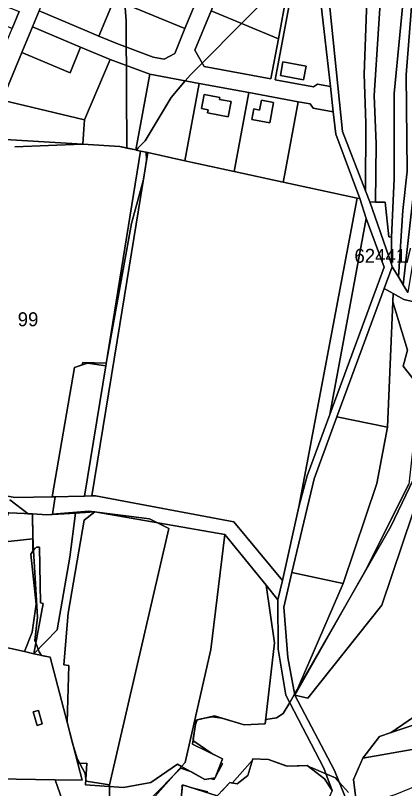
# Model space of a CAD drawing. Extents: x -502026 to -497664, y -1143484 to -1138019.
# Drawn here: x -498740.2 to -498516.2, y -1141619.2 to -1141174.4 of the extents above; entities that cross this region are included whole.
import ezdxf

# ---------------------------------------------------------------- set-up
doc = ezdxf.new("R2010")
doc.units = 0
for name, color, linetype in [('25', 7, 'Continuous'), ('31', 7, 'Continuous'), ('37', 7, 'Continuous'), ('43', 7, 'Continuous'), ('49', 7, 'Continuous'), ('55', 7, 'Continuous'), ('62', 7, 'Continuous'), ('7', 7, 'Continuous')]:
    doc.layers.add(name, color=color, linetype=linetype)

msp = doc.modelspace()

# ---------------------------------------------------------------- linework, layer by layer
at = {"layer": '25'}
for points in [[(-498750.53, -1141150.51), (-498755.96, -1141164.93), (-498738.05, -1141172.05), (-498742.03, -1141181.8), (-498793.83, -1141161.35), (-498790.27, -1141151.29), (-498778.95, -1141139.15)], [(-498730.32, -1141461.17), (-498730.31, -1141475.48), (-498755.37, -1141478.17), (-498750.65, -1141467.55), (-498747.41, -1141468.9), (-498743.97, -1141460.64)], [(-498730.2, -1141482.67), (-498731.44, -1141484.27), (-498728.37, -1141513.04), (-498730.54, -1141529.13), (-498734.96, -1141540.38), (-498760.47, -1141534.79), (-498774.41, -1141531.73), (-498775.27, -1141518.59), (-498770.38, -1141518.64), (-498770.32, -1141512.29), (-498767.95, -1141507.51), (-498759.4, -1141499.21), (-498764.51, -1141493.88), (-498773.09, -1141502.21), (-498777.46, -1141502.69), (-498777.56, -1141496.1), (-498759.62, -1141484.68), (-498758.49, -1141485.19), (-498755.37, -1141478.17), (-498730.31, -1141475.48)]]:
    msp.add_lwpolyline(points, close=True, dxfattribs=at)
at = {"layer": '31'}
msp.add_lwpolyline([(-498760.47, -1141534.79), (-498734.96, -1141540.38), (-498729.72, -1141541.63), (-498720.31, -1141543.62), (-498710.5, -1141581.07), (-498704.3, -1141604.77), (-498701.78, -1141614.38), (-498717.42, -1141614.15), (-498751.28, -1141613.52)], dxfattribs=at)
msp.add_lwpolyline([(-498724.8, -1141582.02), (-498727.01, -1141574.21), (-498729.99, -1141575.05), (-498727.78, -1141582.86)], close=True, dxfattribs=at)
at = {"layer": '37'}
for points in [[(-498538.74, -1141275.38), (-498551.83, -1141241.13), (-498559.88, -1141162.22), (-498559.81, -1141138.76), (-498551.64, -1141125.18), (-498548.32, -1141111.71), (-498535.71, -1141107.87), (-498539.48, -1141208.18), (-498538.43, -1141236.34)], [(-498532.87, -1141281.85), (-498536.19, -1141281.7), (-498538.74, -1141275.38), (-498538.43, -1141236.34), (-498539.48, -1141208.18), (-498535.71, -1141107.87), (-498526.27, -1141105.09), (-498533.65, -1141220.44), (-498532.5, -1141248.33)], [(-498513.1, -1141105.94), (-498515.54, -1141151.64), (-498522.24, -1141219.2), (-498522.17, -1141268.46), (-498523.65, -1141301.86), (-498525.21, -1141301.74), (-498527.35, -1141281.78), (-498532.87, -1141281.85), (-498532.5, -1141248.33), (-498533.65, -1141220.44), (-498526.27, -1141105.09)], [(-498507.19, -1141105.99), (-498515.28, -1141208.6), (-498514.74, -1141264), (-498517.1, -1141286.52), (-498519.76, -1141324.69), (-498523.26, -1141318.93), (-498523.73, -1141317.57), (-498523.65, -1141301.86), (-498522.17, -1141268.46), (-498522.24, -1141219.2), (-498515.54, -1141151.64), (-498513.1, -1141105.94)], [(-498500.85, -1141106.22), (-498506.22, -1141158.67), (-498508.91, -1141208.96), (-498510.44, -1141271.63), (-498516.97, -1141329.28), (-498519.76, -1141324.69), (-498517.1, -1141286.52), (-498514.74, -1141264), (-498515.28, -1141208.6), (-498507.19, -1141105.99)], [(-498495.46, -1141106.76), (-498500.03, -1141158.94), (-498501.24, -1141181.71), (-498505.1, -1141256.75), (-498507.41, -1141291.91), (-498514.23, -1141333.78), (-498516.97, -1141329.28), (-498510.44, -1141271.63), (-498508.91, -1141208.96), (-498506.22, -1141158.67), (-498500.85, -1141106.22)], [(-498661.05, -1141140.4), (-498630.66, -1141152.97), (-498632.69, -1141157.87), (-498642.63, -1141181.9), (-498683.47, -1141165), (-498681.88, -1141161.17), (-498673.53, -1141140.98), (-498671.5, -1141136.07)], [(-498681.88, -1141161.17), (-498683.47, -1141165), (-498692.26, -1141186.25), (-498698.91, -1141183.44), (-498726.58, -1141171.76), (-498716.3, -1141146.93), (-498688.57, -1141158.4)], [(-498627.58, -1141171.69), (-498636.97, -1141194.38), (-498631.63, -1141203.78), (-498593.1, -1141210.93), (-498588.8, -1141187.74), (-498583.95, -1141161.6), (-498617.65, -1141147.67)], [(-498588.8, -1141187.74), (-498627.58, -1141171.69), (-498617.65, -1141147.67), (-498583.95, -1141161.6)], [(-498564.45, -1141166.97), (-498558.89, -1141215.23), (-498566.29, -1141213.86), (-498568.62, -1141215.46), (-498590.64, -1141211.38), (-498581.13, -1141160.07)], [(-498642.63, -1141181.9), (-498648.54, -1141196.2), (-498654.68, -1141199.51), (-498661.02, -1141198.34), (-498681.82, -1141190.57), (-498692.26, -1141186.25), (-498683.47, -1141165)], [(-498588.8, -1141187.74), (-498593.1, -1141210.93), (-498631.63, -1141203.78), (-498636.97, -1141194.38), (-498627.58, -1141171.69)], [(-498702.71, -1141192.63), (-498708.77, -1141207.33), (-498736.5, -1141195.76), (-498730.39, -1141180.99)], [(-498685.75, -1141199.76), (-498700.56, -1141234.44), (-498747.91, -1141223.21), (-498736.5, -1141195.76), (-498708.77, -1141207.33), (-498702.71, -1141192.63)], [(-498662.84, -1141208.17), (-498670.92, -1141251.79), (-498680.04, -1141249.78), (-498701.42, -1141248.47), (-498700.89, -1141239.9), (-498700.56, -1141234.44), (-498685.75, -1141199.76)], [(-498572.87, -1141203.53), (-498586.2, -1141201.08), (-498587.65, -1141208.98), (-498574.32, -1141211.44)], [(-498634.37, -1141213.44), (-498642.62, -1141257.95), (-498663.99, -1141253.32), (-498668.16, -1141252.4), (-498670.92, -1141251.79), (-498662.84, -1141208.17)], [(-498605.91, -1141218.72), (-498614.32, -1141264.08), (-498642.62, -1141257.95), (-498634.37, -1141213.44)], [(-498616.11, -1141223.92), (-498622.73, -1141222.7), (-498622.53, -1141221.65), (-498624.53, -1141221.25), (-498631.64, -1141219.91), (-498633.12, -1141227.93), (-498629.3, -1141228.62), (-498629.65, -1141230.48), (-498617.75, -1141232.67)], [(-498577.44, -1141224), (-498585.12, -1141265.43), (-498586.01, -1141270.21), (-498614.32, -1141264.08), (-498605.91, -1141218.72)], [(-498700.56, -1141234.44), (-498700.89, -1141239.9), (-498701.42, -1141248.47), (-498749.42, -1141245.53), (-498756.04, -1141242.78), (-498747.91, -1141223.21)], [(-498591.56, -1141224.45), (-498598.58, -1141223.16), (-498599.64, -1141228.85), (-498602.98, -1141228.2), (-498604.09, -1141234.25), (-498593.73, -1141236.17)], [(-498557.22, -1141229.78), (-498555.73, -1141242.75), (-498542.01, -1141279.74), (-498543.39, -1141279.44), (-498586.01, -1141270.21), (-498585.12, -1141265.43), (-498577.44, -1141224), (-498570.44, -1141225.29), (-498568.84, -1141227.63)], [(-498642.62, -1141257.95), (-498614.32, -1141264.08), (-498586.01, -1141270.21), (-498543.39, -1141279.44), (-498576.99, -1141457.01), (-498586.55, -1141499.57), (-498614.4, -1141465.78), (-498694.16, -1141450.78), (-498696.28, -1141450.83), (-498680.17, -1141352.1), (-498663.99, -1141253.32)], [(-498542.01, -1141279.74), (-498538.22, -1141291.22), (-498559.19, -1141403.94), (-498572.23, -1141439.2), (-498576.99, -1141457.01), (-498543.39, -1141279.44)], [(-498532.87, -1141281.85), (-498527.35, -1141281.78), (-498525.21, -1141301.74), (-498523.65, -1141301.86), (-498523.73, -1141317.57), (-498536.19, -1141281.7)], [(-498559.19, -1141403.94), (-498538.22, -1141291.22), (-498527.86, -1141319.18)], [(-498522.78, -1141334.44), (-498523.01, -1141339.23), (-498526.07, -1141411.27), (-498555.09, -1141405.35), (-498527.91, -1141331.57)], [(-498497.6, -1141374.03), (-498510.68, -1141384.25), (-498516.95, -1141376.07), (-498514.49, -1141366.87), (-498523.01, -1141339.23), (-498522.78, -1141334.44), (-498516.61, -1141337.89), (-498504.01, -1141340.6), (-498487.53, -1141345.87)], [(-498688.22, -1141375.96), (-498700.45, -1141450.92), (-498719.01, -1141451.31), (-498706.24, -1141376.87), (-498698.71, -1141374.41)], [(-498526.07, -1141411.27), (-498532.1, -1141443.66), (-498551.58, -1141501.21), (-498581.03, -1141494.86), (-498568.18, -1141440.9), (-498555.09, -1141405.35)], [(-498595.94, -1141502.21), (-498591.03, -1141535.35), (-498596.43, -1141581.86), (-498608.52, -1141582.51), (-498625.6, -1141577.35), (-498636.16, -1141579.77), (-498638.35, -1141593.7), (-498620.99, -1141602), (-498625.2, -1141612.92), (-498631.14, -1141613.88), (-498644.52, -1141606.48), (-498642.45, -1141604.15), (-498627.78, -1141539.21), (-498619.69, -1141473.1)], [(-498468.3, -1141600.99), (-498521.83, -1141622.73), (-498543.68, -1141629.6), (-498545.55, -1141614.01), (-498540.19, -1141601.73), (-498472.52, -1141589.85)], [(-498557.86, -1141620.31), (-498579.16, -1141667.75), (-498586.65, -1141683.62), (-498595.46, -1141704.28), (-498611.77, -1141740.81), (-498648.14, -1141728.24), (-498683.59, -1141712.28), (-498669.98, -1141686.66), (-498667.93, -1141675.26), (-498657.61, -1141653.21), (-498650.99, -1141654.52), (-498639.74, -1141648.11), (-498633.36, -1141630.35), (-498644.79, -1141624.98), (-498644.02, -1141617.12), (-498624.09, -1141623.37), (-498616.79, -1141615.76), (-498612.61, -1141616.54), (-498606.51, -1141611.58), (-498603.56, -1141602.08), (-498594.48, -1141602.56), (-498583.73, -1141606.31), (-498572.2, -1141605.96), (-498562.32, -1141613.57)]]:
    msp.add_lwpolyline(points, close=True, dxfattribs=at)
msp.add_lwpolyline([(-498581.13, -1141160.07), (-498590.64, -1141211.38), (-498568.62, -1141215.46), (-498566.29, -1141213.86), (-498558.89, -1141215.23), (-498557.22, -1141229.78), (-498568.84, -1141227.63), (-498570.44, -1141225.29), (-498577.44, -1141224), (-498605.91, -1141218.72), (-498634.37, -1141213.44), (-498662.84, -1141208.17), (-498685.75, -1141199.76), (-498702.71, -1141192.63), (-498730.39, -1141180.99), (-498726.58, -1141171.76), (-498698.91, -1141183.44), (-498692.26, -1141186.25), (-498681.82, -1141190.57), (-498661.02, -1141198.34), (-498654.68, -1141199.51), (-498648.54, -1141196.2), (-498642.63, -1141181.9), (-498632.69, -1141157.87)], dxfattribs=at)
at = {"layer": '43'}
for points in [[(-498701.42, -1141248.47), (-498680.04, -1141249.78), (-498670.92, -1141251.79), (-498668.16, -1141252.4), (-498688.22, -1141375.96), (-498698.71, -1141374.41), (-498706.24, -1141376.87), (-498719.01, -1141451.31), (-498740.54, -1141451.68), (-498760.33, -1141448.11), (-498769.13, -1141441.85), (-498828.34, -1141412.8), (-498749.42, -1141245.53)], [(-498663.99, -1141253.32), (-498680.17, -1141352.1), (-498696.28, -1141450.83), (-498700.45, -1141450.92), (-498688.22, -1141375.96), (-498668.16, -1141252.4)], [(-498619.69, -1141473.1), (-498627.78, -1141539.21), (-498642.45, -1141604.15), (-498644.52, -1141606.48), (-498646.97, -1141605.13), (-498662.29, -1141615.75), (-498677.92, -1141618.49), (-498699.84, -1141617.04), (-498699.04, -1141604.63), (-498704.3, -1141604.77), (-498710.5, -1141581.07), (-498709.54, -1141548.3), (-498712.41, -1141548.04), (-498709.83, -1141518.37), (-498700.61, -1141464.83), (-498694.46, -1141459.99)], [(-498729.72, -1141541.63), (-498724.28, -1141512.69), (-498725.75, -1141512.35), (-498726.47, -1141480.37), (-498728.15, -1141480.3), (-498730.2, -1141482.67), (-498730.31, -1141475.48), (-498730.32, -1141461.17), (-498722.2, -1141461.68), (-498705.72, -1141460.68), (-498708.91, -1141485.96), (-498716.24, -1141527.88)], [(-498729.72, -1141541.63), (-498734.96, -1141540.38), (-498730.54, -1141529.13), (-498728.37, -1141513.04), (-498731.44, -1141484.27), (-498730.2, -1141482.67), (-498728.15, -1141480.3), (-498726.47, -1141480.37), (-498725.75, -1141512.35), (-498724.28, -1141512.69)], [(-498644.52, -1141606.48), (-498698.67, -1141667.49), (-498717.42, -1141614.15), (-498701.78, -1141614.38), (-498704.3, -1141604.77), (-498699.04, -1141604.63), (-498699.84, -1141617.04), (-498677.92, -1141618.49), (-498662.29, -1141615.75), (-498646.97, -1141605.13)], [(-498717.42, -1141614.15), (-498698.67, -1141667.49), (-498695.49, -1141677.7), (-498709.13, -1141683.37), (-498719.96, -1141686.46), (-498736.92, -1141687.62), (-498754.9, -1141684.48), (-498778.26, -1141684.08), (-498776.89, -1141671.76), (-498775.76, -1141662.06), (-498767.62, -1141628.33), (-498773.73, -1141623.84), (-498772.57, -1141613.25), (-498751.28, -1141613.52)]]:
    msp.add_lwpolyline(points, close=True, dxfattribs=at)
for points in [[(-498504.01, -1141340.6), (-498516.61, -1141337.89), (-498522.78, -1141334.44), (-498527.91, -1141331.57), (-498523.26, -1141318.93), (-498519.76, -1141324.69), (-498516.97, -1141329.28), (-498514.23, -1141333.78)], [(-498534.51, -1141663.26), (-498556.46, -1141608.73), (-498579.41, -1141565.45), (-498571.87, -1141567.19), (-498529.35, -1141513.69), (-498493.68, -1141408.31)], [(-498493.68, -1141408.31), (-498529.35, -1141513.69), (-498571.87, -1141567.19), (-498579.41, -1141565.45), (-498538.57, -1141493.43), (-498513.8, -1141444.12)], [(-498698.67, -1141667.49), (-498644.52, -1141606.48), (-498631.14, -1141613.88), (-498625.2, -1141612.92), (-498620.99, -1141602), (-498638.35, -1141593.7), (-498636.16, -1141579.77), (-498625.6, -1141577.35), (-498608.52, -1141582.51), (-498596.43, -1141581.86), (-498591.03, -1141535.35), (-498595.94, -1141502.21), (-498589.12, -1141510.6), (-498588.95, -1141538.99), (-498584.52, -1141565.43), (-498562.69, -1141607.49), (-498557.86, -1141620.31), (-498562.32, -1141613.57), (-498572.2, -1141605.96), (-498583.73, -1141606.31), (-498594.48, -1141602.56), (-498603.56, -1141602.08), (-498606.51, -1141611.58), (-498612.61, -1141616.54), (-498616.79, -1141615.76), (-498624.09, -1141623.37), (-498644.02, -1141617.12), (-498644.79, -1141624.98)], [(-498484.13, -1141559.65), (-498523.91, -1141586.93), (-498530.63, -1141589.19), (-498540.19, -1141601.73), (-498545.55, -1141614.01), (-498543.68, -1141629.6)]]:
    msp.add_lwpolyline(points, dxfattribs=at)
at = {"layer": '49'}
msp.add_lwpolyline([(-498551.58, -1141501.21), (-498579.41, -1141565.45), (-498583.42, -1141543.77), (-498585.78, -1141514.82), (-498581.03, -1141494.86)], close=True, dxfattribs=at)
at = {"layer": '55'}
for points in [[(-498559.88, -1141162.22), (-498551.83, -1141241.13), (-498538.74, -1141275.38), (-498536.19, -1141281.7), (-498523.73, -1141317.57), (-498523.26, -1141318.93), (-498527.91, -1141331.57), (-498555.09, -1141405.35), (-498568.18, -1141440.9), (-498581.03, -1141494.86), (-498585.78, -1141514.82), (-498583.42, -1141543.77), (-498579.41, -1141565.45), (-498556.46, -1141608.73), (-498534.51, -1141663.26)], [(-498557.86, -1141620.31), (-498562.69, -1141607.49), (-498584.52, -1141565.43), (-498588.95, -1141538.99), (-498589.12, -1141510.6), (-498586.55, -1141499.57), (-498576.99, -1141457.01), (-498572.23, -1141439.2), (-498559.19, -1141403.94), (-498527.86, -1141319.18), (-498538.22, -1141291.22), (-498542.01, -1141279.74), (-498555.73, -1141242.75), (-498557.22, -1141229.78), (-498558.89, -1141215.23), (-498564.45, -1141166.97)], [(-498726.58, -1141171.76), (-498730.39, -1141180.99), (-498736.5, -1141195.76), (-498747.91, -1141223.21), (-498756.04, -1141242.78), (-498749.42, -1141245.53), (-498828.34, -1141412.8), (-498829.76, -1141415.87), (-498834.17, -1141425.47), (-498839.96, -1141423.17), (-498837.03, -1141416.6), (-498821.03, -1141380.75), (-498758.67, -1141246.22), (-498768.11, -1141244.74), (-498765, -1141236.91), (-498759.27, -1141223.17), (-498753.52, -1141209.38), (-498748.28, -1141196.51), (-498747.93, -1141195.66), (-498742.03, -1141181.8), (-498738.05, -1141172.05)], [(-498509.53, -1141582.1), (-498523.91, -1141586.93), (-498484.13, -1141559.65)]]:
    msp.add_lwpolyline(points, dxfattribs=at)
for points in [[(-498572.87, -1141203.53), (-498574.32, -1141211.44), (-498587.65, -1141208.98), (-498586.2, -1141201.08)], [(-498616.11, -1141223.92), (-498617.75, -1141232.67), (-498629.65, -1141230.48), (-498629.3, -1141228.62), (-498633.12, -1141227.93), (-498631.64, -1141219.91), (-498624.53, -1141221.25), (-498622.53, -1141221.65), (-498622.73, -1141222.7)], [(-498591.56, -1141224.45), (-498593.73, -1141236.17), (-498604.09, -1141234.25), (-498602.98, -1141228.2), (-498599.64, -1141228.85), (-498598.58, -1141223.16)], [(-498497.6, -1141374.03), (-498509.67, -1141407.77), (-498513.8, -1141444.12), (-498538.57, -1141493.43), (-498579.41, -1141565.45), (-498551.58, -1141501.21), (-498532.1, -1141443.66), (-498526.07, -1141411.27), (-498523.01, -1141339.23), (-498514.49, -1141366.87), (-498516.95, -1141376.07), (-498510.68, -1141384.25)], [(-498769.13, -1141441.85), (-498760.33, -1141448.11), (-498740.54, -1141451.68), (-498719.01, -1141451.31), (-498700.45, -1141450.92), (-498696.28, -1141450.83), (-498694.16, -1141450.78), (-498614.4, -1141465.78), (-498586.55, -1141499.57), (-498589.12, -1141510.6), (-498595.94, -1141502.21), (-498619.69, -1141473.1), (-498694.46, -1141459.99), (-498705.72, -1141460.68), (-498722.2, -1141461.68), (-498730.32, -1141461.17), (-498743.97, -1141460.64), (-498745.03, -1141460.6), (-498747.52, -1141460.52), (-498750.42, -1141459.33), (-498756.41, -1141456.87), (-498780.88, -1141446.84), (-498784.3, -1141445.42), (-498785.36, -1141439.68)], [(-498710.5, -1141581.07), (-498720.31, -1141543.62), (-498729.72, -1141541.63), (-498716.24, -1141527.88), (-498708.91, -1141485.96), (-498705.72, -1141460.68), (-498694.46, -1141459.99), (-498700.61, -1141464.83), (-498709.83, -1141518.37), (-498712.41, -1141548.04), (-498709.54, -1141548.3)], [(-498724.8, -1141582.02), (-498727.78, -1141582.86), (-498729.99, -1141575.05), (-498727.01, -1141574.21)]]:
    msp.add_lwpolyline(points, close=True, dxfattribs=at)
at = {"layer": '62'}
for points in [[(-498686, -1141631.58), (-498686, -1141617.95), (-498686, -1141617), (-498652, -1141469.5), (-498658.36, -1141466.32), (-498663, -1141464), (-498698, -1141459.5), (-498718.91, -1141461.4), (-498717.32, -1141451.27), (-498719.01, -1141451.31), (-498706.24, -1141376.87), (-498701.87, -1141375.44), (-498701.5, -1141374), (-498688, -1141374.5), (-498687.83, -1141373.54), (-498673.5, -1141294), (-498666.53, -1141268.83), (-498664.69, -1141257.57), (-498664.9, -1141253.12), (-498668.16, -1141252.4), (-498670.65, -1141251.85), (-498669.48, -1141250.48), (-498665.5, -1141246.5), (-498650.5, -1141221.5), (-498642.42, -1141211.95), (-498639.5, -1141208.5), (-498632.77, -1141201.77), (-498609.98, -1141178.97), (-498590.07, -1141159.07)], [(-498590.07, -1141159.07), (-498609.98, -1141178.97), (-498632.77, -1141201.77), (-498639.5, -1141208.5), (-498642.42, -1141211.95), (-498650.5, -1141221.5), (-498665.5, -1141246.5), (-498669.48, -1141250.48), (-498670.65, -1141251.85), (-498670.92, -1141251.79), (-498676.04, -1141250.66), (-498676.03, -1141249.73), (-498676.23, -1141218.59), (-498676.33, -1141203.22), (-498676.4, -1141192.59), (-498676.5, -1141177.5), (-498677.3, -1141167.55)], [(-498677.3, -1141167.55), (-498676.5, -1141177.5), (-498676.4, -1141192.59), (-498676.33, -1141203.22), (-498676.23, -1141218.59), (-498676.03, -1141249.73), (-498676.04, -1141250.66), (-498680.04, -1141249.78), (-498701.42, -1141248.47), (-498701.9, -1141248.44), (-498740.5, -1141250)], [(-498740.5, -1141250), (-498701.9, -1141248.44), (-498701.42, -1141248.47), (-498680.04, -1141249.78), (-498676.04, -1141250.66), (-498670.92, -1141251.79), (-498670.65, -1141251.85), (-498668.16, -1141252.4), (-498664.9, -1141253.12), (-498664.69, -1141257.57), (-498666.53, -1141268.83), (-498673.5, -1141294), (-498687.83, -1141373.54), (-498688, -1141374.5), (-498701.5, -1141374), (-498701.87, -1141375.44), (-498706.24, -1141376.87), (-498719.01, -1141451.31), (-498717.32, -1141451.27), (-498718.91, -1141461.4), (-498698, -1141459.5), (-498663, -1141464), (-498658.36, -1141466.32), (-498652, -1141469.5), (-498686, -1141617), (-498699.5, -1141615), (-498699.63, -1141613.81), (-498700, -1141610.5), (-498703.24, -1141604.74), (-498704.5, -1141602.5), (-498707.51, -1141592.49), (-498710.5, -1141581.07), (-498720.31, -1141543.62), (-498725.21, -1141542.58), (-498726.5, -1141540.5), (-498727.1, -1141538.95), (-498728.52, -1141535.25), (-498729, -1141534), (-498727.5, -1141520.5), (-498729.81, -1141482.22), (-498730.31, -1141473.91), (-498730.32, -1141461.17), (-498732.88, -1141461.07), (-498743.5, -1141453)], [(-498494, -1141405.5), (-498524, -1141468.5), (-498549.8, -1141513.24), (-498577.88, -1141561.93), (-498579.53, -1141564.79), (-498582.33, -1141569.64), (-498586, -1141576), (-498590, -1141578.5), (-498596.14, -1141579.38), (-498596.43, -1141581.86), (-498608.52, -1141582.51), (-498621.45, -1141578.6), (-498627, -1141578), (-498633.25, -1141579.1), (-498635.55, -1141579.63), (-498636.56, -1141582.33), (-498637.84, -1141590.46), (-498637.5, -1141592), (-498627.07, -1141599.09), (-498620.99, -1141602), (-498621.8, -1141604.1), (-498621, -1141605), (-498624.75, -1141611.74), (-498625.2, -1141612.92), (-498625.42, -1141612.95), (-498626, -1141614), (-498627.89, -1141613.35), (-498631.14, -1141613.88), (-498638.91, -1141609.58), (-498645, -1141607.5), (-498649.34, -1141611.92), (-498675.5, -1141638.5)], [(-498675.5, -1141638.5), (-498649.34, -1141611.92), (-498645, -1141607.5), (-498638.91, -1141609.58), (-498631.14, -1141613.88), (-498627.89, -1141613.35), (-498626, -1141614), (-498625.42, -1141612.95), (-498625.2, -1141612.92), (-498624.75, -1141611.74), (-498621, -1141605), (-498621.8, -1141604.1), (-498620.99, -1141602), (-498627.07, -1141599.09), (-498637.5, -1141592), (-498637.84, -1141590.46), (-498636.56, -1141582.33), (-498635.55, -1141579.63), (-498633.25, -1141579.1), (-498627, -1141578), (-498621.45, -1141578.6), (-498608.52, -1141582.51), (-498596.43, -1141581.86), (-498596.14, -1141579.38), (-498590, -1141578.5), (-498586, -1141576), (-498582.33, -1141569.64), (-498579.53, -1141564.79), (-498577.88, -1141561.93), (-498549.8, -1141513.24), (-498524, -1141468.5), (-498494, -1141405.5)], [(-498743.5, -1141453), (-498732.88, -1141461.07), (-498730.32, -1141461.17), (-498730.31, -1141473.91), (-498729.81, -1141482.22), (-498727.5, -1141520.5), (-498729, -1141534), (-498728.52, -1141535.25), (-498727.1, -1141538.95), (-498726.5, -1141540.5), (-498725.21, -1141542.58), (-498720.31, -1141543.62), (-498710.5, -1141581.07), (-498707.51, -1141592.49), (-498704.5, -1141602.5), (-498703.24, -1141604.74), (-498700, -1141610.5), (-498699.63, -1141613.81), (-498699.5, -1141615), (-498686, -1141617), (-498686, -1141617.95), (-498686, -1141631.58)], [(-498544.44, -1141623.22), (-498545.55, -1141614.01), (-498540.19, -1141601.73), (-498530.63, -1141589.19), (-498523.91, -1141586.93), (-498509.53, -1141582.1), (-498498.32, -1141583.09), (-498483.89, -1141586.39), (-498472.52, -1141589.85), (-498468.3, -1141600.99), (-498468.16, -1141602.47), (-498468.1, -1141603.07), (-498462.88, -1141603.19), (-498463.01, -1141601.55), (-498419.15, -1141604.2), (-498406.5, -1141604.5), (-498411, -1141624)], [(-498411, -1141624), (-498406.5, -1141604.5), (-498419.15, -1141604.2), (-498463.01, -1141601.55), (-498462.88, -1141603.19), (-498468.1, -1141603.07), (-498468.16, -1141602.47), (-498468.3, -1141600.99), (-498472.52, -1141589.85), (-498483.89, -1141586.39), (-498498.32, -1141583.09), (-498509.53, -1141582.1), (-498523.91, -1141586.93), (-498530.63, -1141589.19), (-498540.19, -1141601.73), (-498545.55, -1141614.01), (-498544.44, -1141623.22)], [(-498621.43, -1141620.6), (-498616.79, -1141615.76), (-498615.5, -1141616), (-498603.79, -1141602.83), (-498603.56, -1141602.08), (-498594.48, -1141602.56), (-498584.53, -1141606.03), (-498581.41, -1141606.24), (-498572.2, -1141605.96), (-498570.93, -1141606.94), (-498570, -1141607), (-498561.5, -1141610.64), (-498556, -1141613), (-498553.69, -1141615.62), (-498548.5, -1141621.5)], [(-498548.5, -1141621.5), (-498553.69, -1141615.62), (-498556, -1141613), (-498561.5, -1141610.64), (-498570, -1141607), (-498570.93, -1141606.94), (-498572.2, -1141605.96), (-498581.41, -1141606.24), (-498584.53, -1141606.03), (-498594.48, -1141602.56), (-498603.56, -1141602.08), (-498603.79, -1141602.83), (-498615.5, -1141616), (-498616.79, -1141615.76), (-498621.43, -1141620.6)], [(-498644.79, -1141624.98), (-498644.16, -1141618.57), (-498644.5, -1141617.5), (-498644.07, -1141617.6), (-498644.02, -1141617.12), (-498637.89, -1141619.04), (-498629.5, -1141621)], [(-498629.5, -1141621), (-498637.89, -1141619.04), (-498644.02, -1141617.12), (-498644.07, -1141617.6), (-498644.5, -1141617.5), (-498644.16, -1141618.57), (-498644.79, -1141624.98)]]:
    msp.add_lwpolyline(points, dxfattribs=at)
at = {"layer": '7'}
msp.add_lwpolyline([(-498472.52, -1141589.85), (-498540.19, -1141601.73), (-498530.63, -1141589.19), (-498523.91, -1141586.93), (-498509.53, -1141582.1), (-498498.32, -1141583.09), (-498483.89, -1141586.39)], close=True, dxfattribs=at)

# ---------------------------------------------------------------- texts
at = {"layer": '62'}
for s, p in [('62441/III.', (-498545.04, -1141316.67)), ('99', (-498738.93, -1141353.17))]:
    msp.add_text(s, height=8, dxfattribs=at).set_placement(p)

doc.saveas('drawing.dxf')
